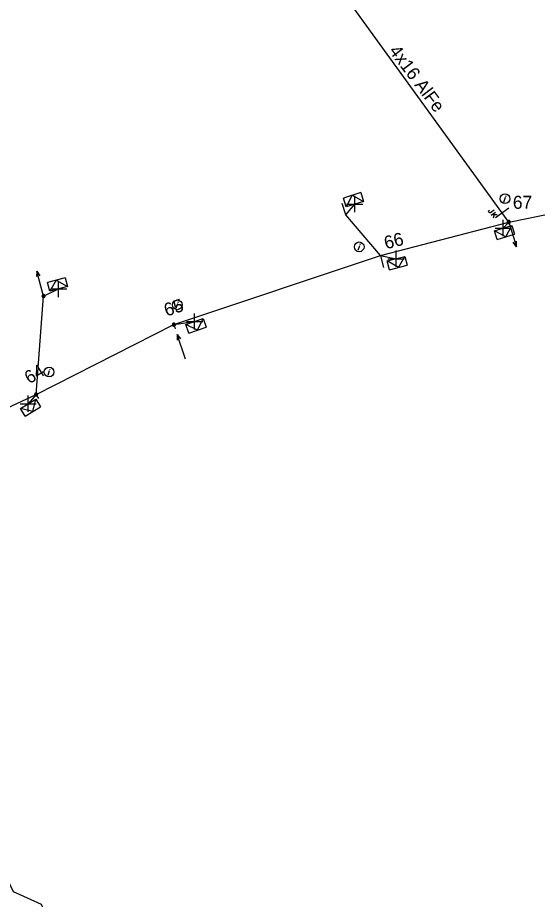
# Model space of a CAD drawing. Extents: x -544780 to -541582, y -1198995 to -1196551.
# Drawn here: x -542681.3 to -542641.2, y -1198149.8 to -1198081.9 of the extents above; entities that cross this region are included whole.
import ezdxf

# ---------------------------------------------------------------- set-up
doc = ezdxf.new("R2010")
doc.units = 0
for name, color, linetype in [('Vrstva 1', 7, 'Continuous'), ('Vrstva 10', 7, 'Continuous'), ('Vrstva 13', 7, 'Continuous'), ('Vrstva 14', 7, 'Continuous'), ('Vrstva 15', 7, 'Continuous'), ('Vrstva 18', 7, 'Continuous'), ('Vrstva 2', 7, 'Continuous'), ('Vrstva 31', 7, 'Continuous'), ('Vrstva 34', 7, 'Continuous'), ('Vrstva 36', 7, 'Continuous'), ('Vrstva 5', 7, 'Continuous'), ('Vrstva 54', 7, 'Continuous'), ('Vrstva 9', 7, 'Continuous')]:
    doc.layers.add(name, color=color, linetype=linetype)

# ---------------------------------------------------------------- blocks, each defined once
blk = doc.blocks.new('NN560')
at = {"layer": 'Vrstva 2'}
for points in [[(1.999, -0.001), (1.59, 0.141)], [(0, -0.001), (1.999, -0.001)], [(1.999, -0.001), (1.59, -0.134)]]:
    blk.add_lwpolyline(points, dxfattribs=at)
blk = doc.blocks.new('NN840')
at = {"layer": 'Vrstva 15'}
for points in [[(0.003, 0.619), (0.003, -0.631)], [(-0.745, -0.71), (-0.745, -0.66)], [(-0.538, -0.385), (-0.538, -0.71)], [(-0.332, -0.385), (-0.332, -0.798)], [(-0.332, -0.641), (-0.125, -0.385)], [(-0.263, -0.557), (-0.091, -0.798)], [(-0.73, -0.764), (-0.745, -0.71)], [(-0.657, -0.798), (-0.73, -0.764)], [(-0.627, -0.798), (-0.657, -0.798)], [(-0.558, -0.764), (-0.627, -0.798)], [(-0.538, -0.71), (-0.558, -0.764)]]:
    blk.add_lwpolyline(points, dxfattribs=at)
blk = doc.blocks.new('NN770')
at = {"layer": 'Vrstva 10'}
for p, q in [((0.002, 0.187), (0.002, 0.263)), ((0.002, -0.276), (0.002, 0.111))]:
    blk.add_line(p, q, dxfattribs=at)
blk.add_circle((0, -0.008), 0.375, dxfattribs=at)
blk = doc.blocks.new('NN800')
at = {"layer": 'Vrstva 1'}
for points in [[(-0.442, 0.442), (0.442, -0.442)], [(-0.442, -0.442), (0.442, 0.442)]]:
    blk.add_lwpolyline(points, dxfattribs=at)
blk = doc.blocks.new('NN630')
at = {"layer": 'Vrstva 9'}
for points in [[(-0.003, -0.7), (-0.703, 0)], [(-0.703, -0.7), (-0.703, 0), (0.697, 0), (0.697, -0.7)], [(-0.003, -0.7), (0.697, 0)], [(-0.703, -0.7), (0.697, -0.7)]]:
    blk.add_lwpolyline(points, dxfattribs=at)
blk = doc.blocks.new('NN500')
at = {"layer": 'Vrstva 2'}
for points in [[(0, -0.24), (0.02, -0.23), (0.05, -0.23), (0.07, -0.22), (0.09, -0.22), (0.12, -0.2), (0.14, -0.19), (0.16, -0.18), (0.17, -0.16), (0.19, -0.14), (0.2, -0.12), (0.21, -0.1), (0.22, -0.07), (0.23, -0.05), (0.23, -0.02), (0.23, 0), (0.23, 0.02), (0.23, 0.05), (0.22, 0.07), (0.21, 0.1), (0.2, 0.12), (0.19, 0.14), (0.17, 0.16), (0.16, 0.17), (0.14, 0.19), (0.12, 0.2), (0.09, 0.21), (0.07, 0.22), (0.05, 0.23), (0.02, 0.23), (0, 0.23), (-0.03, 0.23), (-0.05, 0.23), (-0.07, 0.22), (-0.1, 0.21), (-0.12, 0.2), (-0.14, 0.19), (-0.16, 0.17), (-0.18, 0.16), (-0.19, 0.14), (-0.2, 0.12), (-0.22, 0.1), (-0.22, 0.07), (-0.23, 0.05), (-0.23, 0.02), (-0.24, 0), (-0.23, -0.02), (-0.23, -0.05), (-0.22, -0.07), (-0.22, -0.1), (-0.2, -0.12), (-0.19, -0.14), (-0.18, -0.16), (-0.16, -0.18), (-0.14, -0.19), (-0.12, -0.2), (-0.1, -0.22), (-0.07, -0.22), (-0.05, -0.23), (-0.03, -0.23), (0, -0.24)], [(0, -0.24), (0.02, -0.23), (0.05, -0.23), (0.07, -0.22), (0.09, -0.22), (0.12, -0.2), (0.14, -0.19), (0.16, -0.18), (0.17, -0.16), (0.19, -0.14), (0.2, -0.12), (0.21, -0.1), (0.22, -0.07), (0.23, -0.05), (0.23, -0.02), (0.23, 0), (0.23, 0.02), (0.23, 0.05), (0.22, 0.07), (0.21, 0.1), (0.2, 0.12), (0.19, 0.14), (0.17, 0.16), (0.16, 0.17), (0.14, 0.19), (0.12, 0.2), (0.09, 0.21), (0.07, 0.22), (0.05, 0.23), (0.02, 0.23), (0, 0.23), (-0.03, 0.23), (-0.05, 0.23), (-0.07, 0.22), (-0.1, 0.21), (-0.12, 0.2), (-0.14, 0.19), (-0.16, 0.17), (-0.18, 0.16), (-0.19, 0.14), (-0.2, 0.12), (-0.22, 0.1), (-0.22, 0.07), (-0.23, 0.05), (-0.23, 0.02), (-0.24, 0), (-0.23, -0.02), (-0.23, -0.05), (-0.22, -0.07), (-0.22, -0.1), (-0.2, -0.12), (-0.19, -0.14), (-0.18, -0.16), (-0.16, -0.18), (-0.14, -0.19), (-0.12, -0.2), (-0.1, -0.22), (-0.07, -0.22), (-0.05, -0.23), (-0.03, -0.23), (0, -0.24)], [(0, -0.21), (0.02, -0.2), (0.04, -0.2), (0.06, -0.2), (0.08, -0.19), (0.1, -0.18), (0.12, -0.17), (0.14, -0.15), (0.15, -0.14), (0.16, -0.12), (0.18, -0.1), (0.19, -0.08), (0.19, -0.06), (0.2, -0.04), (0.2, -0.02), (0.2, 0), (0.2, 0.02), (0.2, 0.04), (0.19, 0.06), (0.19, 0.08), (0.18, 0.1), (0.16, 0.12), (0.15, 0.14), (0.14, 0.15), (0.12, 0.17), (0.1, 0.18), (0.08, 0.19), (0.06, 0.19), (0.04, 0.2), (0.02, 0.2), (0, 0.2), (-0.02, 0.2), (-0.04, 0.2), (-0.06, 0.19), (-0.08, 0.19), (-0.1, 0.18), (-0.12, 0.17), (-0.14, 0.15), (-0.15, 0.14), (-0.17, 0.12), (-0.18, 0.1), (-0.19, 0.08), (-0.2, 0.06), (-0.2, 0.04), (-0.21, 0.02), (-0.21, 0), (-0.21, -0.02), (-0.2, -0.04), (-0.2, -0.06), (-0.19, -0.08), (-0.18, -0.1), (-0.17, -0.12), (-0.15, -0.14), (-0.14, -0.15), (-0.12, -0.17), (-0.1, -0.18), (-0.08, -0.19), (-0.06, -0.2), (-0.04, -0.2), (-0.02, -0.2), (0, -0.21)], [(0, -0.18), (0.02, -0.18), (0.04, -0.17), (0.05, -0.17), (0.07, -0.16), (0.09, -0.15), (0.1, -0.14), (0.12, -0.13), (0.13, -0.12), (0.14, -0.1), (0.15, -0.09), (0.16, -0.07), (0.17, -0.05), (0.17, -0.04), (0.17, -0.02), (0.17, 0), (0.17, 0.02), (0.17, 0.04), (0.17, 0.05), (0.16, 0.07), (0.15, 0.09), (0.14, 0.1), (0.13, 0.12), (0.12, 0.13), (0.1, 0.14), (0.09, 0.15), (0.07, 0.16), (0.05, 0.17), (0.04, 0.17), (0.02, 0.17), (0, 0.18), (-0.02, 0.17), (-0.04, 0.17), (-0.06, 0.17), (-0.07, 0.16), (-0.09, 0.15), (-0.1, 0.14), (-0.12, 0.13), (-0.13, 0.12), (-0.14, 0.1), (-0.15, 0.09), (-0.16, 0.07), (-0.17, 0.05), (-0.17, 0.04), (-0.18, 0.02), (-0.18, 0), (-0.18, -0.02), (-0.17, -0.04), (-0.17, -0.05), (-0.16, -0.07), (-0.15, -0.09), (-0.14, -0.1), (-0.13, -0.12), (-0.12, -0.13), (-0.1, -0.14), (-0.09, -0.15), (-0.07, -0.16), (-0.06, -0.17), (-0.04, -0.17), (-0.02, -0.18), (0, -0.18)], [(0, -0.15), (0.01, -0.15), (0.03, -0.14), (0.04, -0.14), (0.06, -0.13), (0.07, -0.13), (0.08, -0.12), (0.1, -0.11), (0.11, -0.1), (0.12, -0.09), (0.13, -0.07), (0.13, -0.06), (0.14, -0.05), (0.14, -0.03), (0.14, -0.02), (0.14, 0), (0.14, 0.01), (0.14, 0.03), (0.14, 0.04), (0.13, 0.06), (0.13, 0.07), (0.12, 0.09), (0.11, 0.1), (0.1, 0.11), (0.08, 0.12), (0.07, 0.13), (0.06, 0.13), (0.04, 0.14), (0.03, 0.14), (0.01, 0.14), (0, 0.15), (-0.02, 0.14), (-0.03, 0.14), (-0.05, 0.14), (-0.06, 0.13), (-0.07, 0.13), (-0.09, 0.12), (-0.1, 0.11), (-0.11, 0.1), (-0.12, 0.09), (-0.13, 0.07), (-0.13, 0.06), (-0.14, 0.04), (-0.14, 0.03), (-0.15, 0.01), (-0.15, 0), (-0.15, -0.02), (-0.14, -0.03), (-0.14, -0.05), (-0.13, -0.06), (-0.13, -0.07), (-0.12, -0.09), (-0.11, -0.1), (-0.1, -0.11), (-0.09, -0.12), (-0.07, -0.13), (-0.06, -0.13), (-0.05, -0.14), (-0.03, -0.14), (-0.02, -0.15), (0, -0.15)], [(0, -0.12), (0.01, -0.12), (0.02, -0.11), (0.03, -0.11), (0.05, -0.11), (0.06, -0.1), (0.07, -0.09), (0.08, -0.09), (0.09, -0.08), (0.09, -0.07), (0.1, -0.06), (0.11, -0.05), (0.11, -0.04), (0.11, -0.02), (0.11, -0.01), (0.12, 0), (0.11, 0.01), (0.11, 0.02), (0.11, 0.04), (0.11, 0.05), (0.1, 0.06), (0.09, 0.07), (0.09, 0.08), (0.08, 0.09), (0.07, 0.09), (0.06, 0.1), (0.05, 0.11), (0.03, 0.11), (0.02, 0.11), (0.01, 0.12), (0, 0.12), (-0.01, 0.12), (-0.03, 0.11), (-0.04, 0.11), (-0.05, 0.11), (-0.06, 0.1), (-0.07, 0.09), (-0.08, 0.09), (-0.09, 0.08), (-0.1, 0.07), (-0.1, 0.06), (-0.11, 0.05), (-0.11, 0.04), (-0.12, 0.02), (-0.12, 0.01), (-0.12, 0), (-0.12, -0.01), (-0.12, -0.02), (-0.11, -0.04), (-0.11, -0.05), (-0.1, -0.06), (-0.1, -0.07), (-0.09, -0.08), (-0.08, -0.09), (-0.07, -0.09), (-0.06, -0.1), (-0.05, -0.11), (-0.04, -0.11), (-0.03, -0.11), (-0.01, -0.12), (0, -0.12)], [(0, -0.09), (0.01, -0.09), (0.02, -0.09), (0.03, -0.08), (0.03, -0.08), (0.04, -0.08), (0.05, -0.07), (0.06, -0.07), (0.06, -0.06), (0.07, -0.05), (0.07, -0.04), (0.08, -0.04), (0.08, -0.03), (0.08, -0.02), (0.09, -0.01), (0.09, 0), (0.09, 0.01), (0.08, 0.02), (0.08, 0.03), (0.08, 0.03), (0.07, 0.04), (0.07, 0.05), (0.06, 0.06), (0.06, 0.06), (0.05, 0.07), (0.04, 0.07), (0.03, 0.08), (0.03, 0.08), (0.02, 0.08), (0.01, 0.09), (0, 0.09), (-0.01, 0.09), (-0.02, 0.08), (-0.03, 0.08), (-0.04, 0.08), (-0.04, 0.07), (-0.05, 0.07), (-0.06, 0.06), (-0.07, 0.06), (-0.07, 0.05), (-0.08, 0.04), (-0.08, 0.03), (-0.08, 0.03), (-0.09, 0.02), (-0.09, 0.01), (-0.09, 0), (-0.09, -0.01), (-0.09, -0.02), (-0.08, -0.03), (-0.08, -0.04), (-0.08, -0.04), (-0.07, -0.05), (-0.07, -0.06), (-0.06, -0.07), (-0.05, -0.07), (-0.04, -0.08), (-0.04, -0.08), (-0.03, -0.08), (-0.02, -0.09), (-0.01, -0.09), (0, -0.09)], [(0, -0.06), (0, -0.06), (0.01, -0.06), (0.02, -0.05), (0.02, -0.05), (0.03, -0.05), (0.03, -0.05), (0.04, -0.04), (0.04, -0.04), (0.05, -0.03), (0.05, -0.03), (0.05, -0.02), (0.05, -0.02), (0.05, -0.01), (0.06, -0.01), (0.06, 0), (0.06, 0.01), (0.05, 0.01), (0.05, 0.02), (0.05, 0.02), (0.05, 0.03), (0.05, 0.03), (0.04, 0.04), (0.04, 0.04), (0.03, 0.05), (0.03, 0.05), (0.02, 0.05), (0.02, 0.05), (0.01, 0.06), (0, 0.06), (0, 0.06), (-0.01, 0.06), (-0.01, 0.06), (-0.02, 0.05), (-0.02, 0.05), (-0.03, 0.05), (-0.03, 0.05), (-0.04, 0.04), (-0.04, 0.04), (-0.05, 0.03), (-0.05, 0.03), (-0.05, 0.02), (-0.06, 0.02), (-0.06, 0.01), (-0.06, 0.01), (-0.06, 0), (-0.06, -0.01), (-0.06, -0.01), (-0.06, -0.02), (-0.05, -0.02), (-0.05, -0.03), (-0.05, -0.03), (-0.04, -0.04), (-0.04, -0.04), (-0.03, -0.05), (-0.03, -0.05), (-0.02, -0.05), (-0.02, -0.05), (-0.01, -0.06), (-0.01, -0.06), (0, -0.06)], [(0, -0.03), (0, -0.03), (0, -0.03), (0.01, -0.03), (0.01, -0.03), (0.01, -0.02), (0.02, -0.02), (0.02, -0.02), (0.02, -0.02), (0.02, -0.02), (0.02, -0.01), (0.02, -0.01), (0.03, -0.01), (0.03, -0.01), (0.03, 0), (0.03, 0), (0.03, 0), (0.03, 0.01), (0.03, 0.01), (0.02, 0.01), (0.02, 0.01), (0.02, 0.02), (0.02, 0.02), (0.02, 0.02), (0.02, 0.02), (0.01, 0.02), (0.01, 0.02), (0.01, 0.03), (0, 0.03), (0, 0.03), (0, 0.03), (0, 0.03), (-0.01, 0.03), (-0.01, 0.03), (-0.01, 0.02), (-0.02, 0.02), (-0.02, 0.02), (-0.02, 0.02), (-0.02, 0.02), (-0.02, 0.02), (-0.03, 0.01), (-0.03, 0.01), (-0.03, 0.01), (-0.03, 0.01), (-0.03, 0), (-0.03, 0), (-0.03, 0), (-0.03, -0.01), (-0.03, -0.01), (-0.03, -0.01), (-0.03, -0.01), (-0.02, -0.02), (-0.02, -0.02), (-0.02, -0.02), (-0.02, -0.02), (-0.02, -0.02), (-0.01, -0.03), (-0.01, -0.03), (-0.01, -0.03), (0, -0.03), (0, -0.03)], [(0.23, 0), (0.7, 0)]]:
    blk.add_lwpolyline(points, dxfattribs=at)
blk = doc.blocks.new('NN510')
at = {"layer": 'Vrstva 2'}
blk.add_lwpolyline([(0.001, 0.002), (0.001, 0.939)], dxfattribs=at)

msp = doc.modelspace()

# ---------------------------------------------------------------- linework, layer by layer
at = {"layer": 'Vrstva 1'}
for points in [[(-542643.45, -1198097.65), (-542662, -1198072.05)], [(-542643.45, -1198097.65), (-542626.56, -1198094.23), (-542603.282, -1198090.95)], [(-542692.25, -1198116.677), (-542679.865, -1198110.927), (-542669.255, -1198105.545), (-542653.34, -1198100.237), (-542643.45, -1198097.65)]]:
    msp.add_lwpolyline(points, dxfattribs=at)
at = {"layer": 'Vrstva 5'}
msp.add_lwpolyline([(-542653.332, -1198207.349), (-542653.838, -1198207.578), (-542655.14, -1198206.56), (-542656.57, -1198203.94), (-542656.14, -1198203.05), (-542658.08, -1198198.3), (-542658.97, -1198197.55), (-542659.11, -1198196.95), (-542663.05, -1198186.9), (-542668.93, -1198173.36), (-542669.58, -1198173.01), (-542671.54, -1198168.63), (-542671.49, -1198167.86), (-542679.46, -1198150.19), (-542681.61, -1198149.22), (-542687.099, -1198137.732), (-542691.764, -1198127.22), (-542694.151, -1198121.507), (-542693.105, -1198118.043), (-542690.729, -1198116.678), (-542691.145, -1198115.951)], dxfattribs=at)
at = {"layer": 'Vrstva 54'}
for points in [[(-542653.34, -1198100.237), (-542656.009, -1198097.106), (-542655.32, -1198096.262)], [(-542643.45, -1198097.65), (-542643.879, -1198098.114)], [(-542653.34, -1198100.237), (-542652.132, -1198100.47)], [(-542679.865, -1198110.927), (-542679.298, -1198103.351), (-542678.136, -1198102.798)], [(-542669.255, -1198105.545), (-542667.656, -1198105.306)], [(-542679.865, -1198110.927), (-542680.479, -1198111.635)]]:
    msp.add_lwpolyline(points, dxfattribs=at)

# ---------------------------------------------------------------- block references
at = {"layer": 'Vrstva 13'}
for name, p, rotation in [('NN510', (-542656.01, -1198097.107), 17.143994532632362), ('NN560', (-542643.45, -1198097.65), -72.69117221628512), ('NN510', (-542653.339, -1198100.236), -165.42815828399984), ('NN560', (-542679.298, -1198103.351), 105.00166389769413), ('NN560', (-542668.371, -1198108.199), 108.521011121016)]:
    msp.add_blockref(name, p, dxfattribs=dict(at, rotation=rotation))
at = {"layer": 'Vrstva 13', "yscale": 0.5}
for p, xscale, rotation in [((-542643.45, -1198097.65), 0.5, -72.69100000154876), ((-542679.298, -1198103.351), 0.5, 105.00199999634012), ((-542669.255, -1198105.545), 0.5, -71.47899993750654), ((-542679.865, -1198110.927), 0.5000000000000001, -58.829000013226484)]:
    msp.add_blockref('NN500', p, dxfattribs=dict(at, xscale=xscale, rotation=rotation))
at = {"layer": 'Vrstva 18', "rotation": -54.07200986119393}
msp.add_blockref('NN840', (-542643.958, -1198096.949), dxfattribs=at)
at = {"layer": 'Vrstva 31'}
for p, rotation in [((-542655.32, -1198096.262), -162.8560055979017), ((-542643.879, -1198098.114), 17.30882782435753), ((-542652.132, -1198100.47), 14.571841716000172), ((-542678.136, -1198102.798), -164.9983361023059), ((-542667.656, -1198105.306), 18.521011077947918), ((-542680.479, -1198111.635), 31.17135006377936)]:
    msp.add_blockref('NN630', p, dxfattribs=dict(at, rotation=rotation))
at = {"layer": 'Vrstva 34'}
for p, rotation in [((-542655.32, -1198096.262), 44.99999995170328), ((-542643.879, -1198098.114), 44.99999995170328), ((-542652.132, -1198100.47), 45), ((-542678.136, -1198102.798), 45.00000009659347), ((-542667.656, -1198105.306), 45), ((-542680.479, -1198111.635), 45)]:
    msp.add_blockref('NN800', p, dxfattribs=dict(at, rotation=rotation))
at = {"layer": 'Vrstva 36', "rotation": -18.70401939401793}
for p in [(-542643.739, -1198095.849), (-542654.972, -1198099.551), (-542668.991, -1198104.015), (-542678.863, -1198109.187)]:
    msp.add_blockref('NN770', p, dxfattribs=at)

# ---------------------------------------------------------------- texts
at = {"layer": 'Vrstva 14'}
msp.add_text('67', height=1, dxfattribs=at).set_placement((-542643.135, -1198096.63))
for s, rotation, p in [('66', 14.572, (-542652.912, -1198099.756)), ('65', 18.521, (-542669.817, -1198104.934)), ('64', 31.171, (-542680.388, -1198110.149))]:
    msp.add_text(s, height=1, rotation=rotation, dxfattribs=at).set_placement(p)
at = {"layer": 'Vrstva 2'}
msp.add_text('4x16 AlFe', height=1, rotation=307.007, dxfattribs=at).set_placement((-542652.727, -1198084.487))

doc.saveas('drawing.dxf')
